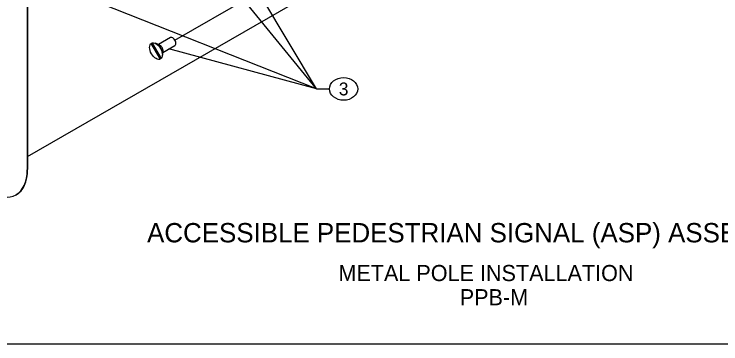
# Model space of a CAD drawing. Extents: x 99862 to 103151, y 100000 to 105076.
# Drawn here: x 100935 to 101811, y 100000 to 100408 of the extents above; entities that cross this region are included whole.
import ezdxf

# ---------------------------------------------------------------- set-up
doc = ezdxf.new("R2010")
doc.units = 0
for name, color, linetype in [('Level 1', 7, 'Continuous'), ('Level 15', 7, 'Continuous'), ('Level 16', 7, 'Continuous'), ('Level 20', 7, 'Continuous'), ('Level 40', 7, 'Continuous'), ('Level 41', 7, 'Continuous')]:
    doc.layers.add(name, color=color, linetype=linetype)

msp = doc.modelspace()

# ---------------------------------------------------------------- linework, layer by layer
at = {"layer": 'Level 1'}
msp.add_lwpolyline([(99862, 99999.5), (103151, 99999.5), (103151, 102075.5), (99862, 102075.5)], close=True, dxfattribs=at)
at = {"layer": 'Level 15'}
for q in [(100999.58, 100695.96), (101126.86, 100622.47), (100999.58, 100438.76), (101126.86, 100365.28), (101325.8, 100315.62)]:
    msp.add_line((101309.8, 100315.62), q, dxfattribs=at)
at = {"layer": 'Level 16'}
for p, q in [((101134.36, 100376.1), (101275.59, 100457.64)), ((100951.77, 100231.71), (101321.47, 100445.16))]:
    msp.add_line(p, q, dxfattribs=at)
at = {"layer": 'Level 20'}
msp.add_ellipse((101343.3, 100315.62), major_axis=(-17.5, 0), ratio=0.8, dxfattribs=at)
at = {"layer": 'Level 40'}
for p, q in [((100951.37, 100675.35), (100951.37, 100215.34)), ((100951.77, 100675.58), (100951.77, 100215.57))]:
    msp.add_line(p, q, dxfattribs=at)
for centre, start_param in [((100903.64, 100242.89), 5.497787), ((100904.04, 100243.12), 6.277293)]:
    msp.add_ellipse(centre, major_axis=(33.75, -58.46), ratio=0.57735, start_param=start_param, end_param=7.068583, dxfattribs=at)
at = {"layer": 'Level 41'}
for p, q in [((101105.93, 100372.59), (101117.1, 100353.23)), ((101128.74, 100379.35), (101113.74, 100370.69)), ((101104.63, 100371.84), (101115.8, 100352.48)), ((101115.02, 100370.18), (101109.64, 100372.32)), ((101119.37, 100360.95), (101134.36, 100369.6)), ((101118.72, 100356.58), (101119.57, 100362.31))]:
    msp.add_line(p, q, dxfattribs=at)
msp.add_ellipse((101110.87, 100362.53), major_axis=(-5.63, 9.74), ratio=0.57735, dxfattribs=at)
for centre, start_param, end_param in [((101131.55, 100374.48), 6.28318, 9.424778), ((101131.55, 100374.48), 3.141593, 3.141605), ((101115.64, 100365.29), 0.630137, 2.511455)]:
    msp.add_ellipse(centre, major_axis=(2.81, -4.87), ratio=0.57735, start_param=start_param, end_param=end_param, dxfattribs=at)

# ---------------------------------------------------------------- texts
at = {"layer": 'Level 20'}
for s, height, p in [('3', 16, (101337.39, 100307.62)), ('ACCESSIBLE PEDESTRIAN SIGNAL (ASP) ASSEMBLY', 24, (101099.78, 100125.35)), ('METAL POLE INSTALLATION', 20, (101336.9, 100077.35)), ('PPB-M', 20, (101487.24, 100047.35))]:
    msp.add_text(s, height=height, dxfattribs=at).set_placement(p)

doc.saveas('drawing.dxf')
